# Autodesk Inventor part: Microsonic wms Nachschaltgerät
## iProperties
Shininess: 64.0
Length Units: 11269
Angle Units: 11279
Time Units: 11290
Mass Units: 11283
Length Display Precision: 3
Angle Display Precision: 2
Compacted: True
Part Number: Microsonic wms Nachschaltgerät
Document SubType Name: Modeling
Created: 2005-08
Material: Kunststoffgehäuse
Designer: Tanck
Manufacturer: Standard
Standards Organization: Custom
Description: wms-4/4 X
Density: 0.0
Volumn: 0.0
Area: 0.0
PropertySet Name: Model Information
Control State: 0
Master: False
Checked Out: False
Last Check In By: Kramp
Last Check In Date: 2005-08-11
Author: Tanck
Title: wms Sensoren
Subject: Nachschaltgerät
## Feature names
1. Grundkörper [Extrusion]
2. Schalthaube [Extrusion]
3. Profilkontur [Extrusion]
4. Klemmenaussparung oben [Extrusion]
5. Klemmenaussparung mitten [Extrusion]
6. Klemmenaussparung unten [Extrusion]
7. Klemmenschlitz [Extrusion]
8. Klemmenaussparungen unten [Mirror]
9. Klemmenaussparungen [Rectangular Pattern]
10. Bodenprofil [Extrusion]
11. Bodenprofil mittig [Extrusion]
12. Vertikale Nut [Extrusion]
13. Nutenstein unten [Extrusion]
14. Nutenstein oben [Extrusion]
15. Nutensteinkehlung [Extrusion]
16. Fase Nutenstein vorn [Chamfer]
17. Versteifung rechts [Extrusion]
18. Versteifung links [Mirror]
19. Versteifung [Fillet]
20. Bohrung oben [Extrusion]
21. Bohrungen oben [Rectangular Pattern]
22. Bohrung unten [Extrusion]
23. Bohrungen unten [Rectangular Pattern]
24. Schraubenkopf oben [Extrusion]
25. Rundung Schraubenkopf oben [Fillet]
26. Schraubenschlitz oben [Extrusion]
27. Kreuzschlitz oben [Extrusion]
28. Schrauben oben [Rectangular Pattern]
29. Schraubenkopf unten [Extrusion]
30. Rundung Schraubenkopf unten [Fillet]
31. Schraubenschlitz unten [Extrusion]
32. Kreuzschlitz unten [Extrusion]
33. Schrauben unten [Rectangular Pattern]
34. Druckschalter [Revolution]
35. Druckschalter vertikal [Rectangular Pattern]
36. Bedienfeldhintergrund [Extrusion]
37. LED wms [Revolution]
38. LED 2 [Rectangular Pattern]
39. LED 3 [Rectangular Pattern]
40. LED 4 [Rectangular Pattern]
41. LED `s horizontal [Rectangular Pattern]
42. LED `s vertikal [Rectangular Pattern]
43. Scheibeschalter [Extrusion]
44. Aussparung [Extrusion]
45. Aussparungen unten [Rectangular Pattern]
46. Aussparungen oben [Mirror]
47. Aussparung oben [Extrusion]
48. Aussparungen [Rectangular Pattern]
49. Schraube innen [Revolution]
50. Klemme innen [Extrusion]
51. Klemmen innen [Rectangular Pattern]
52. Schraube außen [Revolution]
53. Klemme außen [Extrusion]
54. Klemmen außen [Rectangular Pattern]
55. Deckel oben vorn [Extrusion]
56. Deckel seitlich vorn [Extrusion]
57. Halteband vorn
58. Deckel oben hinten [Extrusion]
59. Deckel seitlich hinten [Extrusion]
60. Halteband hinten
61. Deckel außen [Rectangular Pattern]
62. Deckel innen [Rectangular Pattern]
